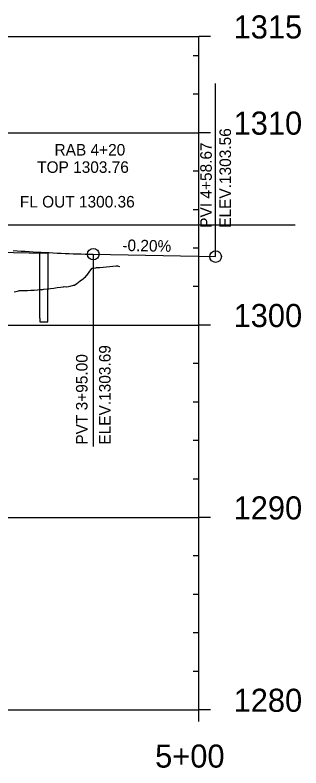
# Model space of a CAD drawing. Extents: x 670877 to 686811, y 705985 to 708501.
# Drawn here: x 685636.5 to 685785.3, y 706297.9 to 706689.3 of the extents above; entities that cross this region are included whole.
import ezdxf

# ---------------------------------------------------------------- set-up
doc = ezdxf.new("R2010")
doc.units = 0
for name, color, linetype in [('30', 7, 'Continuous'), ('37', 7, 'Continuous'), ('Profile Drainage Annotation', 7, 'Continuous'), ('R_Drainage', 7, 'Continuous'), ('R_Exist Surface', 7, 'Continuous'), ('R_No Plot', 7, 'Continuous'), ('R_Vert Alg', 7, 'Continuous'), ('R_Vert Alg Annot', 7, 'Continuous')]:
    doc.layers.add(name, color=color, linetype=linetype)

msp = doc.modelspace()

# ---------------------------------------------------------------- linework, layer by layer
at = {"layer": '37'}
for p, q in [((685232.22, 706678.12), (685732.22, 706678.12)), ((685732.22, 706328.12), (685732.22, 706678.12)), ((685738.22, 706678.12), (685732.22, 706678.12)), ((685732.22, 706668.12), (685729.22, 706668.12)), ((685732.22, 706648.12), (685729.22, 706648.12)), ((685232.22, 706628.12), (685732.22, 706628.12)), ((685738.22, 706628.12), (685732.22, 706628.12)), ((685732.22, 706608.12), (685729.22, 706608.12)), ((685732.22, 706588.12), (685729.22, 706588.12)), ((685732.22, 706568.12), (685729.22, 706568.12)), ((685732.22, 706548.12), (685729.22, 706548.12)), ((685232.22, 706528.12), (685732.22, 706528.12)), ((685738.22, 706528.12), (685732.22, 706528.12)), ((685732.22, 706508.12), (685729.22, 706508.12)), ((685732.22, 706488.12), (685729.22, 706488.12)), ((685732.22, 706468.12), (685729.22, 706468.12)), ((685732.22, 706448.12), (685729.22, 706448.12)), ((685232.22, 706428.12), (685732.22, 706428.12)), ((685738.22, 706428.12), (685732.22, 706428.12)), ((685732.22, 706408.12), (685729.22, 706408.12)), ((685732.22, 706388.12), (685729.22, 706388.12)), ((685732.22, 706368.12), (685729.22, 706368.12)), ((685732.22, 706348.12), (685729.22, 706348.12)), ((685232.22, 706328.12), (685732.22, 706328.12)), ((685738.22, 706328.12), (685732.22, 706328.12)), ((685732.22, 706322.12), (685732.22, 706328.12))]:
    msp.add_line(p, q, dxfattribs=at)
at = {"layer": 'R_Drainage'}
for points in [[(685649.48, 706531.72), (685649.48, 706565.72)], [(685649.48, 706565.72), (685653.48, 706565.72)], [(685653.48, 706565.72), (685653.48, 706546.43)], [(685653.48, 706529.76), (685653.48, 706546.43)], [(685649.48, 706531.72), (685649.48, 706529.76)], [(685649.48, 706529.76), (685653.48, 706529.76)]]:
    msp.add_lwpolyline(points, dxfattribs=at)
at = {"layer": 'R_Exist Surface'}
msp.add_lwpolyline([(685636.12, 706545.48), (685637.83, 706545.84), (685638.85, 706546.05), (685639.55, 706546.07), (685641.26, 706546.14), (685642.97, 706546.21), (685644.68, 706546.29), (685646.39, 706546.38), (685648.1, 706546.48), (685649.81, 706546.59), (685650.94, 706546.67), (685651.53, 706546.74), (685653.24, 706546.96), (685654.95, 706547.18), (685656.66, 706547.4), (685658.37, 706547.63), (685660.08, 706547.85), (685661.79, 706548.08), (685662.06, 706548.12), (685663.32, 706547.99), (685663.51, 706548.04), (685665.22, 706548.46), (685666.93, 706548.89), (685667.2, 706548.96), (685667.39, 706548.85), (685668.64, 706549.78), (685670.35, 706551.07), (685672.06, 706552.37), (685672.42, 706552.64), (685673.13, 706553.22), (685673.58, 706553.71), (685673.77, 706553.95), (685675.49, 706556.16), (685676.63, 706557.65), (685677.2, 706557.74), (685678.56, 706557.99), (685678.91, 706558.01), (685680.62, 706558.14), (685682.33, 706558.28), (685684.04, 706558.42), (685685.75, 706558.56), (685687.47, 706558.71), (685689.18, 706558.86), (685689.75, 706558.92), (685690.89, 706558.63)], dxfattribs=at)
at = {"layer": 'R_No Plot'}
msp.add_line((685182.22, 706580.22), (685782.22, 706580.22), dxfattribs=at)
at = {"layer": 'R_Vert Alg'}
for p, q in [((685627.22, 706565.99), (685652.22, 706565.49)), ((685677.22, 706564.99), (685740.89, 706563.72))]:
    msp.add_line(p, q, dxfattribs=at)
msp.add_lwpolyline([(685635.55, 706566.93), (685637.63, 706566.78), (685639.72, 706566.64), (685641.8, 706566.5), (685643.88, 706566.37), (685645.97, 706566.24), (685648.05, 706566.12), (685650.13, 706566), (685652.22, 706565.89), (685654.3, 706565.79), (685656.38, 706565.69), (685658.47, 706565.59), (685660.55, 706565.5), (685662.63, 706565.42), (685664.72, 706565.34), (685666.8, 706565.27), (685668.88, 706565.2), (685670.97, 706565.14), (685673.05, 706565.09), (685675.13, 706565.04), (685677.22, 706564.99)], dxfattribs=at)
for centre in [(685677.22, 706564.99), (685740.89, 706563.72)]:
    msp.add_circle(centre, 3, dxfattribs=at)
at = {"layer": 'R_Vert Alg Annot'}
for p, q in [((685740.89, 706563.72), (685740.89, 706653.72)), ((685677.22, 706564.99), (685677.22, 706464.99))]:
    msp.add_line(p, q, dxfattribs=at)

# ---------------------------------------------------------------- texts
at = {"layer": '30'}
for s, p in [('1315', (685750.22, 706677.12)), ('1310', (685750.22, 706627.12)), ('1300', (685750.22, 706527.12)), ('1290', (685750.22, 706427.12)), ('1280', (685750.22, 706327.12)), ('5+00', (685709.4, 706298.12))]:
    msp.add_text(s, height=12, dxfattribs=at).set_placement(p)
at = {"layer": 'Profile Drainage Annotation'}
for s, p in [('RAB 4+20', (685657.04, 706616.27)), ('TOP 1303.76', (685648, 706607.27)), ('FL OUT 1300.36', (685639, 706589.27))]:
    msp.add_text(s, height=6, dxfattribs=at).set_placement(p)
at = {"layer": 'R_Vert Alg Annot'}
for s, rotation, p in [('ELEV.1303.56', 90, (685748.89, 706578.72)), ('PVI 4+58.67', 90, (685738.89, 706578.72)), ('-0.20%', 358.8542, (685692.3, 706566.69)), ('ELEV.1303.69', 90, (685686.22, 706465.99)), ('PVT 3+95.00', 90, (685674.22, 706465.99))]:
    msp.add_text(s, height=6, rotation=rotation, dxfattribs=at).set_placement(p)

doc.saveas('drawing.dxf')
